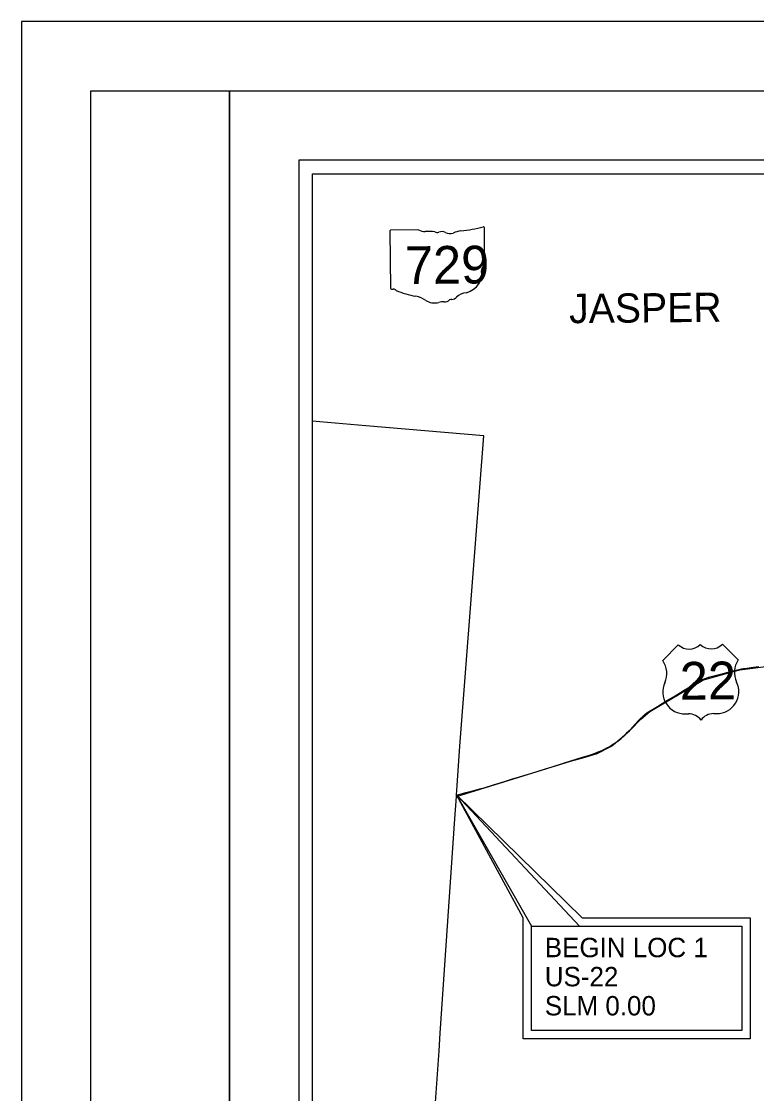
# Model space of a CAD drawing. Extents: x -12 to 164, y -741 to 24.
# Drawn here: x 0 to 5.3, y 14.26 to 22 of the extents above; entities that cross this region are included whole.
import ezdxf

# ---------------------------------------------------------------- set-up
doc = ezdxf.new("R2010")
doc.units = 0
for name, color, linetype in [('Default', 7, 'Continuous'), ('PM_P_Channelizing_Line', 7, 'Continuous'), ('PM_P_Crosswalk', 7, 'Continuous'), ('PM_P_Parking_Lot_Stall', 7, 'Continuous'), ('PM_P_Stop_Line', 7, 'Continuous'), ('PM_X_Channelizing_Line', 7, 'Continuous'), ('SH_Border', 7, 'Continuous'), ('SH_Cut_Line', 7, 'Continuous'), ('SH_Data', 7, 'Continuous'), ('SH_Text', 7, 'Continuous')]:
    doc.layers.add(name, color=color, linetype=linetype)

msp = doc.modelspace()

# ---------------------------------------------------------------- linework, layer by layer
at = {"layer": 'PM_P_Channelizing_Line'}
for points in [[(3.1367, 16.4082), (3.1374, 16.4189), (3.1421, 16.4872), (3.1621, 16.7699), (3.2459, 17.8609), (3.335, 19.0112), (2.4833, 19.0833), (2.1522, 19.1113), (2.1, 19.1158)], [(2.9841, 14.169), (3.0117, 14.5739), (3.0203, 14.7005), (3.1256, 16.2461), (3.1367, 16.4082), (3.9599, 16.6616), (4.0642, 16.6923), (4.134, 16.7129), (4.1465, 16.7165), (4.2593, 16.7732), (4.2671, 16.78), (4.3838, 16.8814), (4.3926, 16.889), (4.466, 16.9654), (4.5324, 17.02), (4.9014, 17.2405), (4.9117, 17.2467), (5.1095, 17.3017), (5.1797, 17.3207), (5.4419, 17.3559)]]:
    msp.add_lwpolyline(points, dxfattribs=at)
at = {"layer": 'PM_P_Crosswalk'}
for points in [[(4.3823, 16.8833), (4.3887, 16.89), (4.4255, 16.9295), (4.4556, 16.9611), (4.4699, 16.9757), (4.4704, 16.9762), (4.4776, 16.9831), (4.481, 16.9864), (4.4886, 16.9932), (4.4986, 17.0012), (4.511, 17.0104), (4.5215, 17.0177), (4.5344, 17.026), (4.5629, 17.0433), (4.5871, 17.058), (4.62, 17.0779), (4.6354, 17.0873), (4.6595, 17.102), (4.7012, 17.1272), (4.7342, 17.1471), (4.7803, 17.175), (4.82, 17.1987), (4.8244, 17.2013), (4.8794, 17.2345), (4.8949, 17.2434), (4.9063, 17.2494), (4.9102, 17.2512), (4.9179, 17.2548), (4.9297, 17.2596), (4.9418, 17.264), (4.954, 17.2678), (4.9738, 17.2732), (5.0608, 17.2956), (5.1056, 17.3069), (5.11, 17.3081), (5.1305, 17.3134), (5.1753, 17.3244), (5.1929, 17.3282), (5.208, 17.331), (5.2308, 17.3345), (5.2791, 17.3411), (5.3173, 17.3464)], [(4.0631, 16.6966), (4.0963, 16.7068), (4.1183, 16.7138), (4.1377, 16.7207), (4.1593, 16.729), (4.1736, 16.7348), (4.19, 16.7422), (4.2039, 16.7489), (4.2221, 16.7584), (4.2378, 16.7672), (4.2533, 16.7764), (4.2706, 16.7875), (4.2855, 16.7977), (4.3001, 16.8082), (4.3123, 16.8176), (4.3242, 16.8274), (4.3376, 16.8394), (4.3526, 16.8534), (4.3709, 16.8715), (4.3823, 16.8833)], [(3.1379, 16.418), (3.2046, 16.4357), (3.2618, 16.4506), (3.3163, 16.4655), (3.3434, 16.4733), (3.4048, 16.4921), (3.4832, 16.5166), (3.5421, 16.5347), (3.5838, 16.5477), (3.6231, 16.5597), (3.6795, 16.5771), (3.7334, 16.594), (3.78, 16.6085), (3.8266, 16.6229), (3.9173, 16.6512), (3.9614, 16.665), (4.0448, 16.6909), (4.0631, 16.6966)]]:
    msp.add_lwpolyline(points, dxfattribs=at)
at = {"layer": 'PM_P_Parking_Lot_Stall'}
for p, q in [((3.3402, 20.2954), (3.3382, 20.5117)), ((2.6573, 20.4879), (2.6612, 20.0744)), ((2.8634, 20.497), (2.664, 20.4951)), ((3.3402, 20.2954), (3.3402, 20.2954))]:
    msp.add_line(p, q, dxfattribs=at)
for centre, major_axis, start_param, end_param in [((3.0904, 21.0629), (0.7222, 0.0068), 4.814394, 5.042369), ((3.3306, 20.5125), (0.00758, 0.00007), 6.141152, 7.989035), ((2.6651, 20.4889), (0.00789, 0.00007), 1.712693, 3.28349), ((2.9105, 20.5454), (0.0765, 0.0007), 4.042523, 4.731795), ((2.9385, 20.2655), (0.2747, 0.0026), 1.404758, 1.657858), ((2.9987, 20.4942), (0.0221, 0.0002), 3.836095, 5.185415), ((3.0315, 20.4467), (0.0459, 0.0004), 0.950623, 2.079405), ((3.0902, 20.5128), (0.0552, 0.0005), 4.081561, 5.145723), ((3.189, 20.3737), (0.1453, 0.0014), 1.699011, 2.107814), ((3.3386, 20.2795), (0.0117, 0.0001), 1.883978, 3.671073), ((3.2642, 20.2514), (0.0704, 0.0007), 5.934695, 6.695948), ((3.3321, 20.2945), (0.00811, 0.00008), 5.05454, 6.418171), ((3.1392, 20.1754), (0.1806, 0.0017), 5.101752, 6.440018), ((3.3682, 20.2051), (0.0512, 0.0005), 2.387724, 3.262537), ((2.6691, 20.0736), (0.00796, 0.00007), 3.00124, 4.508301), ((2.6699, 20.1159), (0.0607, 0.0006), 4.665946, 4.897461), ((2.683, 20.0508), (0.0219, 0.0002), 0.519207, 1.627899), ((2.956, 20.4249), (0.5215, 0.0049), 4.195997, 4.488961), ((3.2174, 19.9635), (0.0989, 0.0009), 1.647645, 2.488434), ((2.8055, 19.89), (0.1632, 0.0015), 0.823519, 1.323587), ((2.9805, 20.0515), (0.1035, 0.001), 4.026481, 4.996735), ((3.0417, 19.9091), (0.0851, 0.0008), 1.495662, 1.94098), ((3.0482, 20.0212), (0.0552, 0.0005), 4.691044, 5.507374), ((3.0985, 19.9816), (0.0155, 0.0001), 1.147584, 2.315152), ((3.0913, 20.0384), (0.0584, 0.0005), 4.937069, 5.64225)]:
    msp.add_ellipse(centre, major_axis=major_axis, ratio=0.8, start_param=start_param, end_param=end_param, dxfattribs=at)
at = {"layer": 'PM_P_Stop_Line'}
for p, q in [((4.7367, 17.5029), (4.6243, 17.3883)), ((5.1691, 17.3934), (5.0546, 17.5059)), ((4.7868, 17.0039), (4.8095, 17.0041)), ((4.9911, 17.0058), (5.0138, 17.006))]:
    msp.add_line(p, q, dxfattribs=at)
for centre, radius, start, end in [((4.8154, 17.5847), 0.1135, 226.11154, 314.96555), ((4.9743, 17.5862), 0.1135, 226.11154, 314.96555), ((4.495, 17.2959), 0.1589, 335.08567, 35.53948), ((5.3002, 17.3035), 0.1589, 145.53762, 205.99142), ((4.7836, 17.1628), 0.1589, 155.37047, 271.17681), ((5.0141, 17.1649), 0.1589, 269.90028, 25.70663), ((4.8106, 16.8906), 0.1135, 37.40844, 90.53855), ((4.9922, 16.8923), 0.1135, 90.53855, 143.66865)]:
    msp.add_arc(centre, radius, start, end, dxfattribs=at)
at = {"layer": 'SH_Border'}
for points in [[(0.5, 21.5), (1.5, 21.5), (1.5, 0.5), (0.5, 0.5)], [(1.5, 21.5), (33.5, 21.5), (33.5, 0.5), (1.5, 0.5)]]:
    msp.add_lwpolyline(points, close=True, dxfattribs=at)
at = {"layer": 'SH_Cut_Line'}
msp.add_lwpolyline([(0, 0), (34, 0), (34, 22), (0, 22)], close=True, dxfattribs=at)
at = {"layer": 'SH_Data'}
for points in [[(6.9766, 21), (2, 21), (2, 8.9058), (12.1655, 8.9058), (12.1655, 18.6562)], [(12.0655, 18.6562), (12.0655, 9.0058), (2.1, 9.0058), (2.1, 20.9), (6.9766, 20.9)]]:
    msp.add_lwpolyline(points, dxfattribs=at)
for points in [[(4.0254, 15.4714), (3.1374, 16.4189), (3.6777, 15.4714)], [(3.6777, 15.4714), (5.1948, 15.4714), (5.1948, 14.72), (3.6777, 14.72)]]:
    msp.add_lwpolyline(points, close=True, dxfattribs=at)
at = {"layer": 'SH_Text'}
for p, q in [((3.1374, 16.4189), (4.0439, 15.5314)), ((3.6177, 15.5314), (3.1374, 16.4189)), ((3.6177, 14.66), (3.6177, 15.5314)), ((4.0439, 15.5314), (5.2548, 15.5314)), ((5.2548, 15.5314), (5.2548, 14.66)), ((5.2548, 14.66), (3.6177, 14.66))]:
    msp.add_line(p, q, dxfattribs=at)

# ---------------------------------------------------------------- texts
at = {"layer": 'Default'}
for s, p in [('BEGIN LOC 1', (3.774, 15.2481)), ('US-22', (3.774, 15.0381)), ('SLM 0.00', (3.774, 14.8281))]:
    msp.add_text(s, height=0.14, dxfattribs=at).set_placement(p)
at = {"layer": 'PM_P_Parking_Lot_Stall'}
msp.add_text('729', height=0.27243, rotation=0.53855, dxfattribs=at).set_placement((2.7666, 20.1046))
at = {"layer": 'PM_P_Stop_Line'}
msp.add_text('22', height=0.27243, rotation=0.53855, dxfattribs=at).set_placement((4.7486, 17.1057))
at = {"layer": 'PM_X_Channelizing_Line'}
msp.add_text('JASPER', height=0.21134, rotation=0.53856, dxfattribs=at).set_placement((3.9504, 19.8226))

doc.saveas('drawing.dxf')
